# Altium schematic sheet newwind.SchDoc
size A3
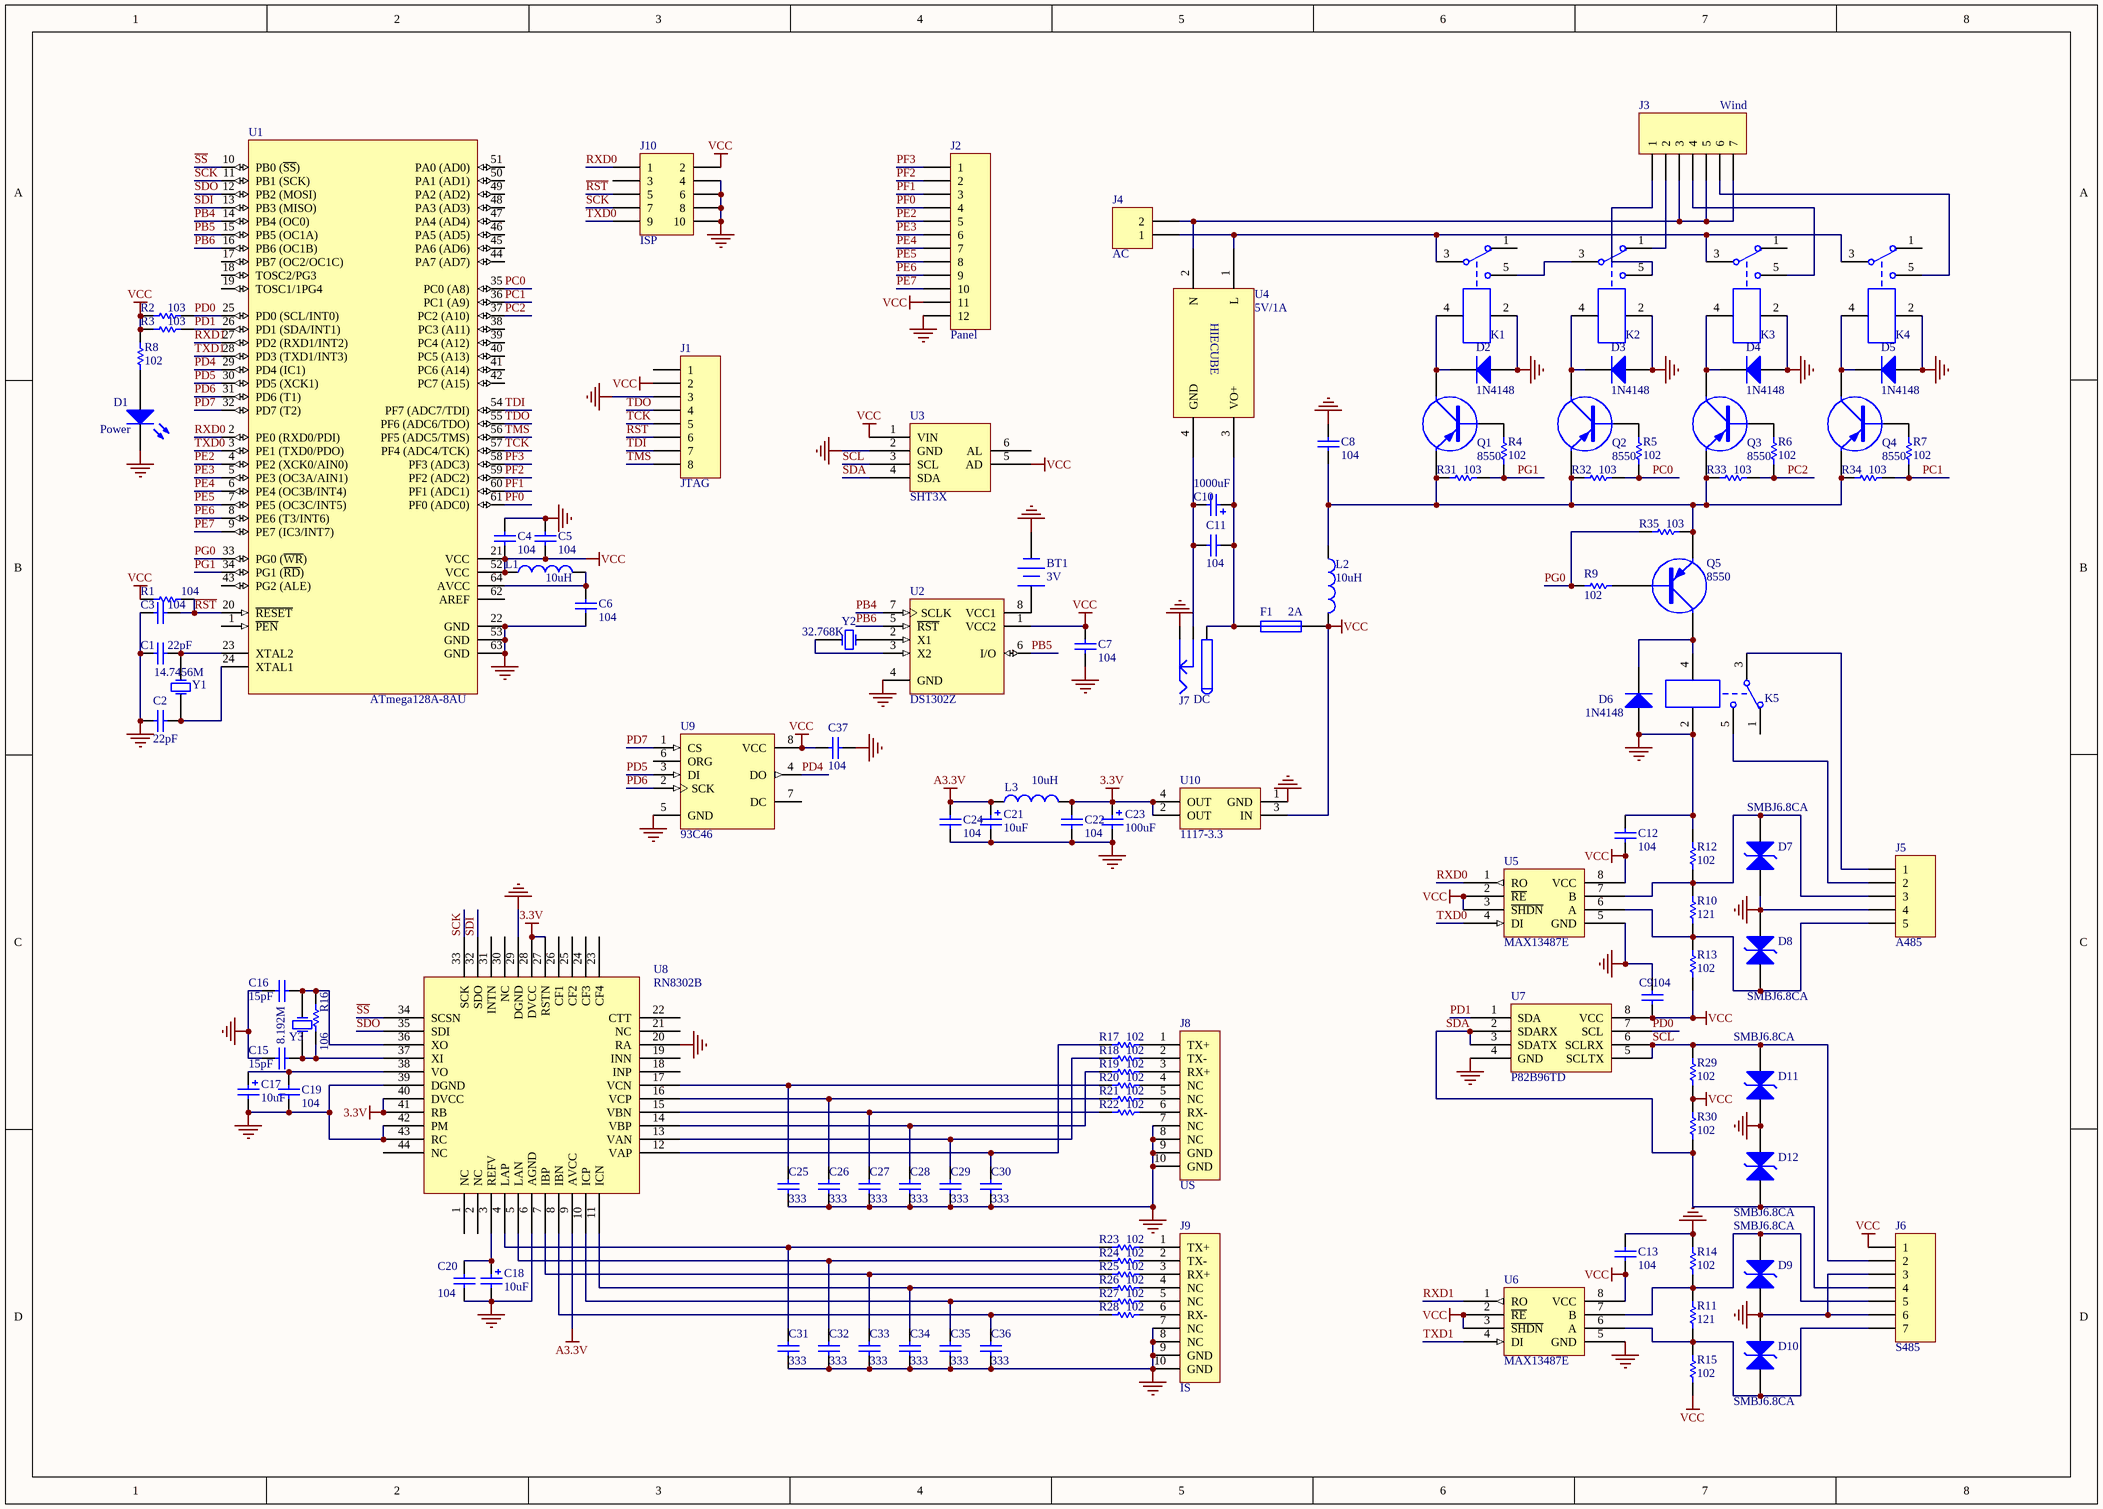
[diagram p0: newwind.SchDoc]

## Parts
BT1  3V  [CR2032]
C1  22pF  [0805]
C2  22pF  [0805]
C3  104  [0805]
C4  104  [0805]
C5  104  [0805]
C6  104  [0805]
C7  104  [0805]
C8  104  [0805]
C9  104  [0805]
C10  1000uF  [C10]
C11  104  [0805]
C12  104  [0805]
C13  104  [0805]
C15  15pF  [0805]
C16  15pF  [0805]
C17  10uF  [C1206]
C18  10uF  [C1206]
C19  104  [0805]
C20  104  [0805]
C21  10uF  [C1206]
C22  104  [0805]
C23  100uF  [C1210]
C24  104  [0805]
C25  333  [0805]
C26  333  [0805]
C27  333  [0805]
C28  333  [0805]
C29  333  [0805]
C30  333  [0805]
C31  333  [0805]
C32  333  [0805]
C33  333  [0805]
C34  333  [0805]
C35  333  [0805]
C36  333  [0805]
C37  104  [0805]
D1  Power  [LED-2P]
D2  1N4148  [1206]
D3  1N4148  [1206]
D4  1N4148  [1206]
D5  1N4148  [1206]
D6  1N4148  [1206]
D7  SMBJ6.8CA  [SMB]
D8  SMBJ6.8CA  [SMB]
D9  SMBJ6.8CA  [SMB]
D10  SMBJ6.8CA  [SMB]
D11  SMBJ6.8CA  [SMB]
D12  SMBJ6.8CA  [SMB]
F1  2A  [1812]
J1  JTAG  [CON8]
J2  Panel  [XH2.54-12P]
J3  Wind  [2EDG-3.81-7P]
J4  AC  [2EDG-3.81-2P]
J5  A485  [2EDG-3.81-5P]
J6  S485  [2EDG-3.81-7P]
J7  DC  [PWR2.5]
J8  US  [RJ-45]
J9  IS  [RJ-45]
J10  ISP  [DC3-10]
K1  (no value)  [T73]
K2  (no value)  [T73]
K3  (no value)  [T73]
K4  (no value)  [T73]
K5  (no value)  [T73]
L1  10uH  [0805]
L2  10uH  [0805]
L3  10uH  [0805]
Q1  8550  [SOT-23-3]
Q2  8550  [SOT-23-3]
Q3  8550  [SOT-23-3]
Q4  8550  [SOT-23-3]
Q5  8550  [SOT-23-3]
R1  104  [0805]
R2  103  [0805]
R3  103  [0805]
R4  102  [0805]
R5  102  [0805]
R6  102  [0805]
R7  102  [0805]
R8  102  [0805]
R9  102  [0805]
R10  121  [0805]
R11  121  [0805]
R12  102  [0805]
R13  102  [0805]
R14  102  [0805]
R15  102  [0805]
R16  106  [0805]
R17  102  [0805]
R18  102  [0805]
R19  102  [0805]
R20  102  [0805]
R21  102  [0805]
R22  102  [0805]
R23  102  [0805]
R24  102  [0805]
R25  102  [0805]
R26  102  [0805]
R27  102  [0805]
R28  102  [0805]
R29  102  [0805]
R30  102  [0805]
R31  103  [0805]
R32  103  [0805]
R33  103  [0805]
R34  103  [0805]
R35  103  [0805]
U1  ATmega128A-8AU  [ATMega128]
U2  DS1302Z  [SOP-8P-3.9]
U3  SHT3X  [SHT3X]
U4  5V/1A  [HIECUBE12W]
U5  MAX13487E  [SOP-8P-3.9]
U6  MAX13487E  [SOP-8P-3.9]
U7  P82B96TD  [SOP-8P-3.9]
U8  RN8302B  [QFP-44P-0.8]
U9  93C46  [SOP-8P-3.9]
U10  1117-3.3  [SOT-223]
Y1  14.7456M  [CRYSTAL-2P]
Y2  32.768K  [32.768K]
Y3  8.192M  [CRYSTAL-2P]

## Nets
3.3V: C22.2 C23.1 L3.2 U8.27(RSTN) U8.28(DVCC) U8.40(DVCC) U8.41(RB) U10.2(OUT) U10.4(OUT)
A3.3V: C21.1 C24.2 L3.1 U8.9(AVCC)
GND: BT1.2(-) C1.1 C2.1 C3.1 C4.2 C5.2 C6.1 C7.1 C8.2 C9.2 C12.2 C13.1 C15.1 C16.2 C17.2 C18.2 C19.2 C20.1 C21.2 C22.1 C23.2 C24.1 C25.2 C26.2 C27.2 C28.2 C29.2 C30.2 C31.2 C32.2 C33.2 C34.2 C35.2 C36.2 C37.2 D1.2(K) D2.1(A) D3.1(A) D4.1(A) D5.1(A) D6.1(A) D7.2(K) D8.1(A) D9.2(K) D10.1(A) D11.2(K) D12.1(A) J1.3 J2.12 J5.4 J6.3 J6.6 J7.2 J8.7(NC) J8.8(NC) J8.9(GND) J8.10(GND) J9.7(NC) J9.8(NC) J9.9(GND) J9.10(GND) J10.4 J10.6 J10.8 J10.10 K1.2 K2.2 K3.2 K4.2 K5.2 R12.2 R14.2 U1.22(GND) U1.53(GND) U1.63(GND) U2.4(GND) U3.2(GND) U5.5(GND) U6.5(GND) U7.4(GND) U8.6(AGND) U8.20(RA) U8.29(DGND) U8.39(DGND) U8.42(PM) U8.43(RC) U9.5(GND) U10.1(GND)
VCC: C4.1 C5.1 C7.2 C9.1 C12.1 C13.2 C37.1 F1.2 J1.2 J2.11 J6.1 J10.2 L1.1 L2.2 R1.1 R2.1 R3.1 R8.2 R13.1 R15.1 R29.1 R30.2 U1.21(VCC) U1.52(VCC) U2.1(VCC2) U3.1(VIN) U3.5(AD) U5.2(~{RE}) U5.3(~{SHDN}) U5.8(VCC) U6.2(~{RE}) U6.3(~{SHDN}) U6.8(VCC) U7.8(VCC) U9.8(VCC) U10.3(IN)
PB4: U1.14(PB4_(OC0)) U2.7(SCLK)
PB5: U1.15(PB5_(OC1A)) U2.6(I/O)
PB6: U1.16(PB6_(OC1B)) U2.5(~{RST})
PC0: R5.1 R32.2 U1.35(PC0_(A8))
PC1: R7.1 R34.2 U1.36(PC1_(A9))
PC2: R6.1 R33.2 U1.37(PC2_(A10))
PD0: R2.2 U1.25(PD0_(SCL/INT0)) U7.7(SCL)
PD1: R3.2 U1.26(PD1_(SDA/INT1)) U7.1(SDA)
PD4: U1.29(PD4_(IC1)) U9.4(DO)
PD5: U1.30(PD5_(XCK1)) U9.3(DI)
PD6: U1.31(PD6_(T1)) U9.2(SCK)
PD7: U1.32(PD7_(T2)) U9.1(CS)
PE2: J2.5 U1.4(PE2_(XCK0/AIN0))
PE3: J2.6 U1.5(PE3_(OC3A/AIN1))
PE4: J2.7 U1.6(PE4_(OC3B/INT4))
PE5: J2.8 U1.7(PE5_(OC3C/INT5))
PE6: J2.9 U1.8(PE6_(T3/INT6))
PE7: J2.10 U1.9(PE7_(IC3/INT7))
PF0: J2.4 U1.61(PF0_(ADC0))
PF1: J2.3 U1.60(PF1_(ADC1))
PF2: J2.2 U1.59(PF2_(ADC2))
PF3: J2.1 U1.58(PF3_(ADC3))
PG0: R9.2 R35.1 U1.33(PG0_(~{WR}))
PG1: R4.1 R31.2 U1.34(PG1_(~{RD}))
~{RST}: C3.2 J1.6 J10.5 R1.2 U1.20(~{RESET})
RXD0: J10.1 U1.2(PE0_(RXD0/PDI)) U5.1(RO)
RXD1: U1.27(PD2_(RXD1/INT2)) U6.1(RO)
~{SS}: U1.10(PB0_(~{SS})) U8.34(SCSN)
SCK: J10.7 U1.11(PB1_(SCK)) U8.33(SCK)
SCL: D11.1(A) J6.2 R29.2 U3.3(SCL) U7.5(SCLTX) U7.6(SCLRX)
SDA: D12.2(K) J6.4 R30.1 U3.4(SDA) U7.2(SDARX) U7.3(SDATX)
SDI: U1.13(PB3_(MISO)) U8.32(SDO)
SDO: U1.12(PB2_(MOSI)) U8.35(SDI)
TCK: J1.5 U1.57(PF4_(ADC4/TCK))
TDI: J1.7 U1.54(PF7_(ADC7/TDI))
TDO: J1.4 U1.55(PF6_(ADC6/TDO))
TMS: J1.8 U1.56(PF5_(ADC5/TMS))
TXD0: J10.9 U1.3(PE1_(TXD0/PDO)) U5.4(DI)
TXD1: U1.28(PD3_(TXD1/INT3)) U6.4(DI)
NetBT1_1: BT1.1(+) U2.8(VCC1)
NetC1_2: C1.2 U1.23(XTAL2) Y1.2(OSC2)
NetC2_2: C2.2 U1.24(XTAL1) Y1.1(OSC1)
NetC6_2: C6.2 L1.2 U1.64(AVCC)
NetC8_1: C8.1 L2.1 Q1.2(E) Q2.2(E) Q3.2(E) Q4.2(E) Q5.2(E) R31.1 R32.1 R33.1 R34.1 R35.2
NetC10_1: C10.1 C11.1 F1.1 J7.1 U4.3(VO+)
NetC10_2: C10.2 C11.2 J7.3 U4.4(GND)
NetC15_2: C15.2 R16.1 U8.37(XI) Y3.1(OSC1)
NetC16_1: C16.1 R16.2 U8.36(XO) Y3.2(OSC2)
NetC17_1: C17.1 C19.1 U8.38(VO)
NetC18_1: C18.1 C20.2 U8.3(REFV)
NetC25_1: C25.1 R20.1 U8.17(VCN)
NetC26_1: C26.1 R21.1 U8.16(VCP)
NetC27_1: C27.1 R22.1 U8.15(VBN)
NetC28_1: C28.1 R19.1 U8.14(VBP)
NetC29_1: C29.1 R18.1 U8.13(VAN)
NetC30_1: C30.1 R17.1 U8.12(VAP)
NetC31_1: C31.1 R23.1 U8.4(LAP)
NetC32_1: C32.1 R24.1 U8.5(LAN)
NetC33_1: C33.1 R25.1 U8.7(IBP)
NetC34_1: C34.1 R26.1 U8.11(ICN)
NetC35_1: C35.1 R27.1 U8.10(ICP)
NetC36_1: C36.1 R28.1 U8.8(IBN)
NetD1_1: D1.1(A) R8.1
NetD2_2: D2.2(K) K1.4 Q1.3(C)
NetD3_2: D3.2(K) K2.4 Q2.3(C)
NetD4_2: D4.2(K) K3.4 Q3.3(C)
NetD5_2: D5.2(K) K4.4 Q4.3(C)
NetD6_2: D6.2(K) K5.4 Q5.3(C)
NetD7_1: D7.1(A) J5.3 R10.2 R12.1 U5.7(B)
NetD8_2: D8.2(K) J5.5 R10.1 R13.2 U5.6(A)
NetD9_1: D9.1(A) J6.5 R11.2 R14.1 U6.7(B)
NetD10_2: D10.2(K) J6.7 R11.1 R15.2 U6.6(A)
NetJ3_1: J3.1 K2.5
NetJ3_2: J3.2 K2.1
NetJ3_3: J3.3 J3.5 J3.7 J4.2 U4.2(N)
NetJ3_4: J3.4 K3.5
NetJ3_6: J3.6 K4.5
NetJ4_1: J4.1 K1.3 K3.3 K4.3 U4.1(L)
NetJ5_1: J5.1 K5.3
NetJ5_2: J5.2 K5.5
NetJ8_1: J8.1(TX+) R17.2
NetJ8_2: J8.2(TX-) R18.2
NetJ8_3: J8.3(RX+) R19.2
NetJ8_4: J8.4(NC) R20.2
NetJ8_5: J8.5(NC) R21.2
NetJ8_6: J8.6(RX-) R22.2
NetJ9_1: J9.1(TX+) R23.2
NetJ9_2: J9.2(TX-) R24.2
NetJ9_3: J9.3(RX+) R25.2
NetJ9_4: J9.4(NC) R26.2
NetJ9_5: J9.5(NC) R27.2
NetJ9_6: J9.6(RX-) R28.2
NetK1_5: K1.5 K2.3
NetQ1_1: Q1.1(B) R4.2
NetQ2_1: Q2.1(B) R5.2
NetQ3_1: Q3.1(B) R6.2
NetQ4_1: Q4.1(B) R7.2
NetQ5_1: Q5.1(B) R9.1
NetU2_2: U2.2(X1) Y2.1(OSC1)
NetU2_3: U2.3(X2) Y2.2(OSC2)

Not connected (* = marked no-connect by the designer): J1 1; J10 3; K1 1; K3 1; K4 1; K5 1; U1 1(~{PEN}) 17(PB7_(OC2/OC1C)) 18(TOSC2/PG3) 19(TOSC1/1PG4) 38(PC3_(A11)) 39(PC4_(A12)) 40(PC5_(A13)) 41(PC6_(A14)) 42(PC7_(A15)) 43(PG2_(ALE)) 44(PA7_(AD7)) 45(PA6_(AD6)) 46(PA5_(AD5)) 47(PA4_(AD4)) 48(PA3_(AD3)) 49(PA2_(AD2)) 50(PA1_(AD1)) 51(PA0_(AD0)) 62(AREF); U3 6(AL); U8 1(NC) 2(NC) 18(INP) 19(INN) 21(NC) 22(CTT) 23(CF4) 24(CF3) 25(CF2) 26(CF1) 30(NC) 31(INTN) 44(NC); U9 6(ORG) 7(DC)

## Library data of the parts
BT1 = Battery: Multicell Battery
C1-C9 C11-C13 C15 C16 C19 C20 C22 C24-C37 = Cap1: Capacitor
C10 C17 C18 C21 C23 = Cap2: 电解电容
D1 = LED: Typical INFRARED GaAs LED
D2-D6 = Diode: Default Diode
D7-D12 = TVS
F1 = Fuse 1: Fuse
J1 = MHDR1X8: Header, 8-Pin
J2 = Header 12: Header, 12-Pin
J3 J6 = MHDR1X7: Header, 7-Pin
J4 = MHDR1X2: Header, 2-Pin
J5 = MHDR1X5: Header, 5-Pin
J7 = PWR2.5: 2.5电源插座
J8 J9 = RJ45: RJ45水晶座
J10 = Header 5X2: Header, 5-Pin, Dual row
K1-K5 = Relay-6P: 6脚继电器
L1 = Inductor
L2 L3 = Inductor: Code_IEC: 1005
Q1-Q5 = 8550: PNP三极管
R1-R35 = Res: Resistor
U1 = ATmega128L-8AC: 8-Bit AVR Microcontroller with 128K Bytes of In-System Programmable Flash Memory
U2 = DS1302Z: Trickle Charge Timekeeping Chip
U4 = HIECUBE12W: 12W单输出模块
U9 = 93C46: SPI EEPROM; Note: Do Not Use pin number 7 (DU).
U10 = 1117: 800mA 稳压; PackageDocument: revC
Y1-Y3 = CRYSTAL-2: Crystal Oscillator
